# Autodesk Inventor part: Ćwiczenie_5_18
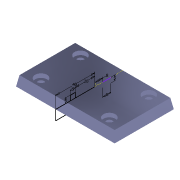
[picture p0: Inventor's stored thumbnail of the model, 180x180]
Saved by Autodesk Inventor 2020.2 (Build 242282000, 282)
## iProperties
Created: 2005-03
Part Number: Ćwiczenie_5_18
Document SubType Name: Modeling
Designer: F.Stasiak
Manufacturer: Standard
Standards Organization: Custom
Density: 1 g/cm^3
Material: Ogólny
Appearance: Chrom - niebieski polerowany
Manager: www.cadconsulting.pl
Company: Fabian Stasiak CAD Consulting
Author: F.Stasiak
Subject: Zbiór ćwiczeń. Autodesk Inventor 2020. Kurs podstawowy
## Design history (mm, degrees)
sketch "Szkic1"
  geometry: L1 (-50, 30)-(50, 30); L2 (50, 30)-(50, -30); L3 (50, -30)-(-50, -30); L4 (-50, -30)-(-50, 30); L5 (0, 30)-(0, -30); 2 further points
  constraints: 10 end point, 3 midpoint, 2 parallel, 1 coincident, 1 horizontal, 1 perpendicular
  dimensions: "d0" = 100 distance of L2.end L3.end; "d1" = 60 distance of L3.end L1.start
extrude "Wyciągnięcie proste1" new body sketch "Szkic1" distance "d2" = 10; taper "d3" = -10 deg
sketch "Szkic3"
  geometry: L1 (-34.641, 20)-(34.641, 20); L2 (34.641, 20)-(34.641, -20); L3 (34.641, -20)-(-34.641, -20); L4 (-34.641, -20)-(-34.641, 20); L5 (0, 20)-(0, -20); A1 r 40 centre (0, 0) between (-34.641, 20) and (34.641, -20); 6 further points
  constraints: 10 end point, 6 coincident, 3 midpoint, 2 parallel, 2 point on circle, 1 centre point, 1 horizontal, 1 perpendicular
  dimensions: "d7" = 80 diameter of A1; "d8" = 40 distance of L3.end L1.start (= 0.5 x d7)
hole "Otwór1" sketch "Szkic3" at (-34.641, 20), (34.641, 20), (34.641, -20), (-34.641, -20) diameter "d9" = 6; stored, may be unused: countersink angle "d13" = 90 deg, drill point angle "d15" = 118 deg; dims "d10" = 6, "d11" = 12, "d12" = 4, "d14" = 8
sketch "Szkic4"
  geometry: L1 (0, -1)-(0, 13) reference; L2 (-28.237, 10)-(28.237, 10) reference; L3 (8, 10)-(16, 10); L4 (16, 10)-(16, 5); L5 (16, 5)-(8, 5); L6 (8, 5)-(8, 10); L7 (-30, 0)-(30, 0) reference; L8 (0, 10)-(-40, 10); L9 (-40, 10)-(-40, 0); L10 (-40, 0)-(0, 0); L11 (28.237, 10)-(-28.237, 10) reference; L12 (30, 0)-(-30, 0) reference; L13 (-25, 15)-(-20, 15); L14 (-20, 15)-(-20, 10); L15 (-20, 10)-(-25, 10); L16 (-25, 10)-(-25, 15)
  constraints: 22 end point, 5 parallel, 4 perpendicular, 3 collinear, 2 horizontal, 2 point on line
  dimensions: "d22" = 5 distance of L3.end L4.end; "d23" = 8 distance of L4.end L5.end; "d24" = 8 distance between parallel lines of L6 L1; "d27" = 40 distance of L8.start L8.end; "d28" = 20 distance between parallel lines of L14 L1; "d29" = 5 distance of L13.start L13.end; "d30" = 5 distance of L15.end L13.start
node "Bryła1"
node "Korpusy bryłowe"
node "Korpusy powierzchniowe"
